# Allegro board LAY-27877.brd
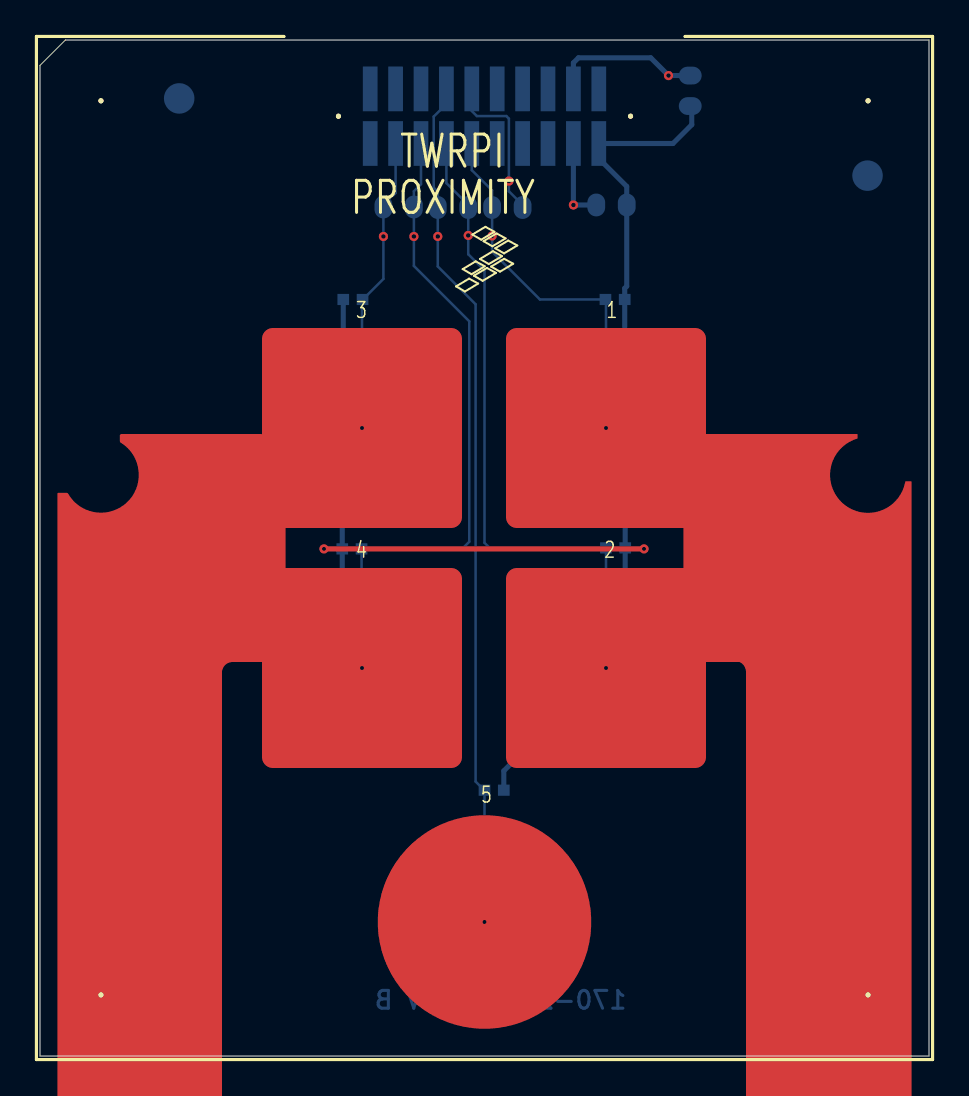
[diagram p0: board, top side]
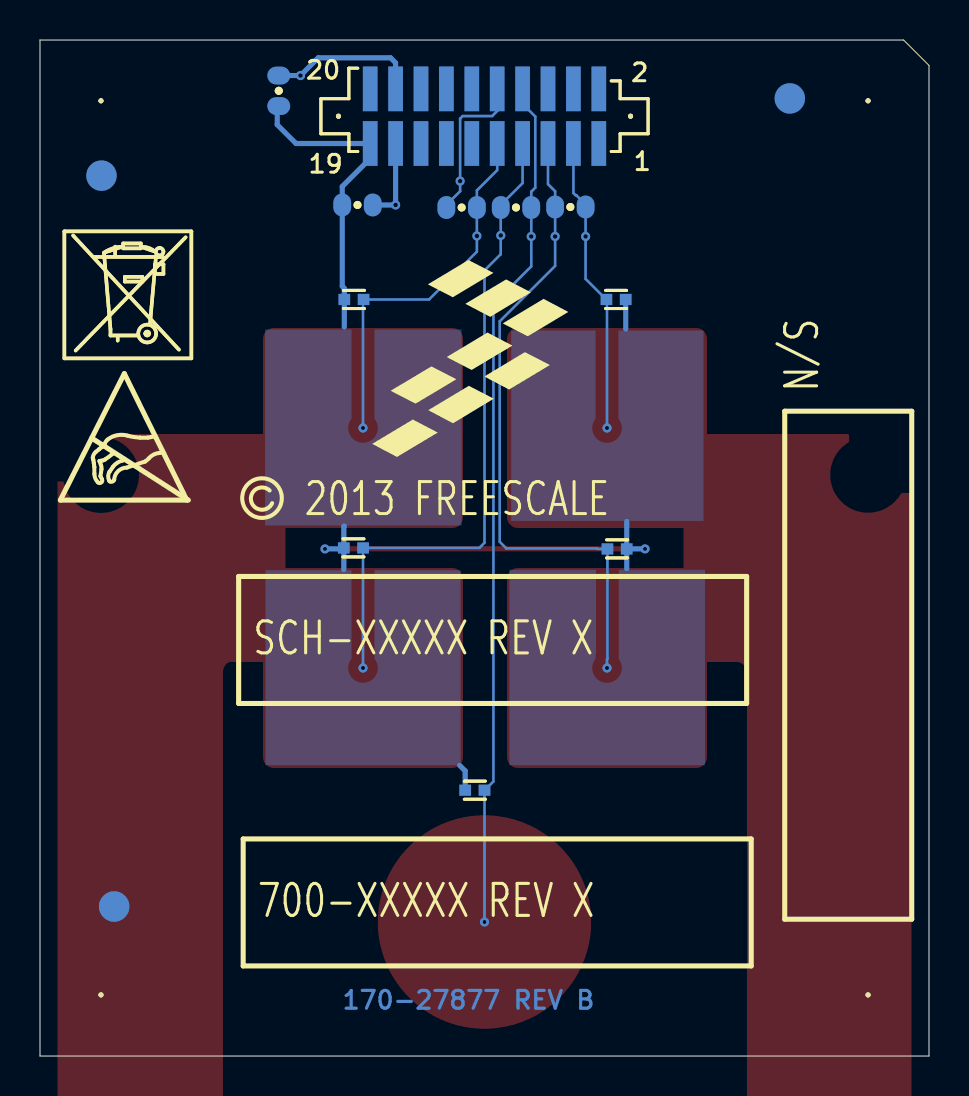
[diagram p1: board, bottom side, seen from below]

Outline 44.45 x 50.8 mm; copper layers: TOP, BOTTOM. Coordinates in mm from the lower left corner of the outline.
Outline path: 0,49.53 0,0 44.45,0 44.45,50.8 1.27,50.8 0,49.53

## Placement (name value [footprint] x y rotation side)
J1  SFC-110-T2-L-D-A  [CON_SFC_20F_50_SM]  22.23 46.99 180 bottom
NOREF  -  []  41.3 0 90 top
NOREF#2  -  []  16.1 31.4 0 top
NOREF#3  -  []  306.55 40.77 0 top
NOREF#4  -  []  -28.78 -30.63 0 top
NOREF#5  -  []  3.05 3.05 0 top
NOREF#6  -  []  -24.77 0.13 270 top
NOREF#7  -  []  -279.74 259.95 0 top
NOREF#8  -  []  41.4 3.05 90 top
NOREF#9  -  []  44.45 0 90 top
NOREF#10  -  []  -0.11 49.41 0 top
NOREF#11  -  []  1.27 50.8 0 top
NOREF#12  -  []  -305.14 -266.46 0 top
NOREF#13  -  []  2.92 0 90 top
NOREF#14  -  []  41.4 3.05 90 top
NOREF#15  -  []  41.4 3.05 0 top
NOREF#16  -  []  0 49.53 45 top
NOREF#17  -  []  44.45 0 90 top
NOREF#18  -  []  12.2 38.32 0 top
NOREF#19  -  []  32.25 50.8 0 top
NOREF#20  -  []  0 0 0 top
NOREF#21  -  []  3.05 3.05 0 top
NOREF#22  -  []  0 50.8 0 top
NOREF#23  -  []  36.35 11.49 0 top
NOREF#24  -  []  20.75 32.24 180 bottom
NOREF#25  -  []  27.41 30.36 180 bottom
NOREF#26  -  []  32.44 5.82 180 bottom
NOREF#27  -  [unnamed#2]  6.96 47.88 180 bottom
NOREF#28  -  []  75.74 33.69 180 bottom
NOREF#29  -  []  44.83 33 180 bottom
NOREF#30  -  [unnamed#2]  40.74 7.47 180 bottom
NOREF#31  -  []  32.66 16.38 180 bottom
NOREF#32  -  [unnamed#2]  41.38 44.02 180 bottom
NOREF#33  -  []  5.77 30.33 270 bottom
NOREF#34  -  []  38 9.38 90 bottom
R1  18K  [RC0603_OV]  28.58 42.55 0 bottom
R2  0  [RC0603_OV]  32.51 48.26 270 bottom
R3  1.0M  [RC0603_OV]  17.93 42.45 0 bottom
R4  1.0M  [RC0603_OV]  20.65 42.42 0 bottom
R5  1.0M  [RC0603_OV]  23.37 42.42 180 bottom
TVS1  PGB2010402KRHF  [DIODE_0402]  15.65 37.83 180 bottom
TVS2  PGB2010402KRHF  [DIODE_0402]  15.6 25.36 180 bottom
TVS3  PGB2010402KRHF  [DIODE_0402]  28.78 25.41 0 bottom
TVS4  PGB2010402KRHF  [DIODE_0402]  22.71 13.29 0 bottom
TVS5  PGB2010402KRHF  [DIODE_0402]  28.75 37.83 0 bottom
U1  Electrode  [ELECTRODE_5P_44X48]  22.23 6.7 0 top

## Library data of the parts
J1 = CONN_HDR_10X2
R1-R5 = RES
TVS1-TVS5 = DIODE_TVS_BIDIR
U1 = ELECTRODE5

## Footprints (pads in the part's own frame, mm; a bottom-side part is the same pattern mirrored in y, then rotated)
CON_SFC_20F_50_SM
  round 0.254 hole 1.346 unplated: (-7.303,0) (7.303,0)
  rect 0.737x2.235 smd: 1(5.715,-1.365) 2(5.715,1.365) 3(4.445,-1.365) 4(4.445,1.365) 5(3.175,-1.365) 6(3.175,1.365) 7(1.905,-1.365) 8(1.905,1.365) 9(0.635,-1.365) 10(0.635,1.365) 11(-0.635,-1.365) 12(-0.635,1.365) 13(-1.905,-1.365) 14(-1.905,1.365) 15(-3.175,-1.365) 16(-3.175,1.365) 17(-4.445,-1.365) 18(-4.445,1.365) 19(-5.715,-1.365) 20(-5.715,1.365)
DIODE_0402
  rect 0.584x0.559 smd: 1(-0.483,0) 2(0.483,0)
ELECTRODE_5P_44X48
  round 0.254 hole 3.175 unplated: (-19.177,41.056) (-19.177,-3.648) (19.177,41.056) (19.177,-3.648)
  custom 2.5x2.5 smd: 1(6.075,24.697) 2(6.075,12.697) 3(-6.125,24.697) 4(-6.125,12.697)
  custom 10.675x10.675 smd: 5(0,-0.003)
RC0603_OV
  oval 0.889x1.143 smd: 1(-0.762,0) 2(0.762,0)
unnamed#2
  round 1.524 smd: (0,0)

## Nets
GND: J1.19 R1.2 R2.2 TVS1.2(A2) TVS2.2(A2) TVS3.2(A2) TVS4.2(A2) TVS5.2(A2)
ELEC_IN0: J1.3 R3.1 TVS1.1(A1) U1.3(E2)
ELEC_IN1: J1.5 R3.2 TVS2.1(A1) U1.4(E3)
ELEC_IN2: J1.7 R4.2 TVS3.1(A1) U1.2(E1)
ELEC_IN3: J1.8 R4.1 TVS4.1(A1) U1.5(E4)
ELEC_IN4: J1.9 R5.2 TVS5.1(A1) U1.1(E0)
ELEC_IN5: J1.10 R5.1
ELEC_IN6: J1.11
ELEC_IN7: J1.12
ELEC_IN8: J1.13
ELEC_IN9: J1.14
ELEC_IN10: J1.15
ELEC_IN11: J1.16
ID0: J1.17 R1.1
ID1: J1.18 R2.1

Pads without a net: J1 1 2 4 6 20

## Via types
v1: diameter 0.457, hole 0.229, TOP to BOTTOM, 8 vias
v2: diameter 0.457, hole 0.203, TOP to BOTTOM, 7 vias

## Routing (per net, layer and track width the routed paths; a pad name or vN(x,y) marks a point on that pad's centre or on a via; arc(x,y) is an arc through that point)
GND: length 41.1
  TOP w0.254: v2(14.2,25.36) v2(30.2,25.36)
  BOTTOM w0.254: 23.47,14.54 23.19,14.26 TVS4.2 ; TVS3.2 29.26,26.47 29.24,26.5 ; TVS3.2 29.31,25.36 v2(30.2,25.36) ; TVS3.2 29.26,24.31 ; TVS1.2 15.16,36.35 ; 29.24,36.46 TVS5.2 29.24,38.39 29.34,38.49 R1.2 29.34,43.48 27.94,44.88 J1.19 31.65,45.62 32.59,46.56 32.59,47.42 R2.2 ; TVS2.2 15.11,26.73 ; TVS2.2 v2(14.2,25.36) ; TVS2.2 15.11,24.36
ELEC_IN0: length 14.9
  BOTTOM w0.127: v2(16.1,31.4) 16.1,37.8 TVS1.1 16.14,37.83 17.17,38.86 v1(17.17,40.98) R3.1 17.17,42.58 17.64,43.04 17.67,43.04 17.78,43.15 J1.3
ELEC_IN1: length 32.7
  BOTTOM w0.127: J1.5 19.05,43.59 18.69,43.24 R3.2 v1(18.69,40.98) 18.69,39.5 21.46,36.73 21.46,25.71 21.13,25.38 16.61,25.38 16.59,25.36 TVS2.1 16.08,19.87 16.1,19.84 v2(16.1,19.4)
ELEC_IN2: length 32.9
  BOTTOM w0.127: J1.7 20.32,43.64 21.41,42.55 R4.2 v1(21.41,41.03) 21.41,40.09 22.23,39.27 22.23,25.66 22.48,25.41 TVS3.1 28.3,25.4 v2(28.3,19.4)
ELEC_IN3: length 43
  BOTTOM w0.127: v2(22.23,6.7) TVS4.1 22.21,13.29 21.78,13.72 21.78,37.59 19.89,39.48 v1(19.89,40.98) R4.1 19.89,43.21 19.69,43.41 19.69,46.97 20.32,47.61 J1.8
ELEC_IN4: length 18.9
  BOTTOM w0.127: J1.9 21.59,44.29 22.61,43.28 R5.2 v1(22.61,41) 22.61,40.21 24.99,37.83 TVS5.1 28.3,37.8 v2(28.3,31.4)
ELEC_IN5: length 7.8
  BOTTOM w0.127: J1.10 21.59,47.25 21.84,47 23.32,47 23.44,46.87 v1(23.44,43.75) 23.44,43.24 24.13,42.55 R5.1
ID0: length 4.2
  BOTTOM w0.254: J1.17 v1(26.67,42.55) R1.1
ID1: length 7.6
  BOTTOM w0.254: J1.18 26.67,49.66 26.92,49.91 30.54,49.91 v1(31.43,49.02) R2.1

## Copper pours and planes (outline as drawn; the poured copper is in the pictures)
GND on BOTTOM: 23.24,36.46 23.24,26.4 33.32,26.4 33.32,36.46
GND on BOTTOM: 11.15,36.4 11.15,26.63 21.08,26.63 21.08,36.4
GND on BOTTOM: 11.07,24.44 11.07,14.41 21.11,14.41 21.11,24.44
GND on BOTTOM: 23.29,24.42 23.29,14.41 33.3,14.41 33.3,24.42

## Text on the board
BOTTOM: 170-27877 REV B | 5 | SECONDARY SIDE
Board Geometry/Soldermask Bottom: 6 | SECONDARY SOLDERMASK
Package Geometry/Pastemask Bottom: 8 | SECONDARY SOLDERPASTE
Ref Des/Silkscreen Bottom: 7 | SECONDARY SILKSCREEN
TOP: 4 | PRIMARY SIDE
Board Geometry/Soldermask Top: 3 | PRIMARY SOLDERMASK
Package Geometry/Pastemask Top: 1 | PRIMARY SOLDERPASTE
Ref Des/Silkscreen Top: 2 | PRIMARY SILKSCREEN | PROXIMITY | TWRPI
DIMENSION: PRIMARY DATUM | GRID ORIGIN | -.120 | 0
User.11: TWRPI-KEYPAD BOARD Rev.A
User.16: 8 | 7 | 1 | 2
User.39: ON SECONDARY SIDE SILKSCREENS | 16. | 17. | 8
User.45: 3.2 | 4 | GN2 PLANE   - LAYER 2  1 OZ. CU. | GN3 PLANE   - LAYER 3  1 Oz. Cu. | BOTTOM SIDE - LAYER 4  SIGNAL LAYER | TOP SIDE    - LAYER 1  SIGNAL LAYER | 4. Impedance Requirements: | 7. Thermal relief: | 7.1 Thermal relief has not been provided for the | 7.2 Thermal relief may be provided by the | 5. Layer stack is as follows: | 6. PCB thickness: As per customer order. | 1. All instructions mentioned herein overrides | 2. Instructions in purchase order also overrides | 3. Incase of any clarifications or contradicting instructions, | 90 ohms, Differential, on 0.1764 mm width tracks. | general instructions. | Please call or email: | Company: Manipal Dot Net Pvt Ltd., Manipal, INDIA. | Cell : 91-98452-43213 | e-mail : pcbinfo@manipal.net | negative layers. | manufacturer as appropriate. | Board specific Instructions: | OF 8 | B | GND PLANE REMOVED FROM L2 | 05-23-13 | D.S. | 1.Specifications: | 6.2 Registration to be +/- .005" and must pass peel test. | 7.2 Electrical test report (BBT) is to be provided along with PCB's. | 12.0 PCB's are to confirm to IPC-A-600D standards. | 1.0 Producibility study- it is the responsibility of the supplier to conduct | 1.1 This drawing is to be used in conjuction with the provided gerber and | 2.Material: | 2.0 NEMA Grade FR-4/Epoxy class , foil lamination structure for core and | 2.1 Color is vendor's option. | 6.Silkscreen: | 6.0 Silksceen using white non-conductive epoxy or equivalent ( both sides ). | 6.1 No Silkscreen allowed on exposed lands or in holes (burnout with soldermask) | 7.Electrical Test: | 7.0 All boards shall be 100% elecrically tested for open/shorts. | 7.1 Apply test stamp in non legend area on the solder side of PCB. | 8.Cleanlines: | 8.0 Boards shall be free of fiber glass dust or any other forgien material. | 8.1 Finished boards must conform to 0.01 MG/IN max NAcl ionic contamonation | 9.Packaging: | 9.0 There shall be max of 25 units per package wrapped in sulpher and silicone | 10.Bow and Twist: | 10.0 Bow and twist to be .007" per Inch or .090 max according to IPC-A-600D. | 11.Inspection: | 11.0 Automatic optical inspection of all layers is required. | 3.Soldermask: | 3.0 Soldermask both sides with (green color) liquid photoimageble soldermask | 4. Drilling: | 4.0 All hole diameters are finished sizes. | 4.1 All holes to be +/- .003" from the true postion unless otherwise specified. | 4.3 An CNC drill file has been supplied - see drill table. | 5.Finish: | 5.0 Plate thru with copper .001" min to .002" max thickness drill size. | 5.1 Solder dip and hot air level with 63/37% tin/lead cpating, .0002" min to | 5.2 Finished boards shall not have nicks, scratches, voids, exposed copper, | thorough review of the artwork and media for manufacturablity in the | supplier's process compliance to all applicable specifications. The | customer must be advised in writing (inadvance of manufacturing) of any | changes, revisions, or corrections made or recommendations to ensure | conformance to the customers standards, and of any specifications that | cannot met. | drill data where applicable. | copper thickness: type GFN, Grade A, Class 1, Class A. | as measured bu omega meter 600SMD. | free material and contained in heavy cardboard cartons with sufficient | surrounding material to prevent shipping damage. | .003 max. thickness. Soldermask over bare copper. | dimensions apply after plating. | .001" max. | poor plating, or misdrilled holes. | General Instructions: | ALL ARE FINISHED DRILL SIZES | FIGURE | SIZE | 8.0 | 53.0 | 125.0 | BY LAYER: TOP to BOTTOM | ALL UNITS ARE IN MILS | TOLERANCE | +0.0/-8.0 | +3.0/-3.0 | PLATED | NON-PLATED | QTY | 7 | 2 | 1
